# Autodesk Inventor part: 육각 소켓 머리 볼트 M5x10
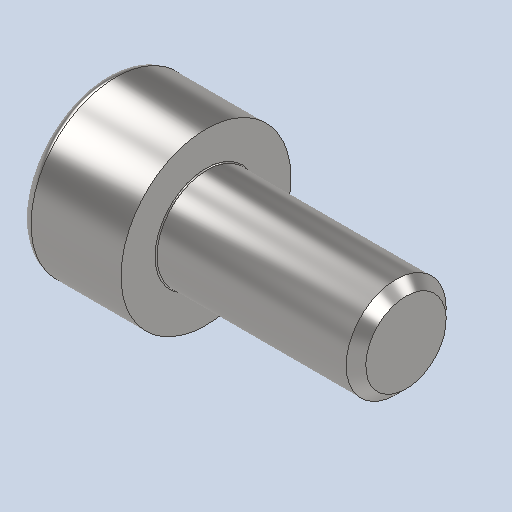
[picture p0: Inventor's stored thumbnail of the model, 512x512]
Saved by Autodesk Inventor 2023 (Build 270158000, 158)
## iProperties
Created: 2024-09
Part Number: 육각 소켓 머리 볼트 M5x10
Material: 강철, 연강
Description: 6각머리 태핑 나사
Document SubType Name: Modeling
Designer: home
Density: 7.85 g/cm^3
Appearance: 기본값
Author: jhkim
Sending System: Autodesk Inventor 2025
Preprocessor: ST-DEVELOPER v20
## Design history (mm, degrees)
feature "Solid1"
node "솔리드1"
